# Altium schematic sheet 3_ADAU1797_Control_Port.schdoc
size 307 x 218 mm; Symbol: Drawing-Symbol_A4; Device: Drawing-Symbol_A4; @Project Name: Slowpoke; @Page Count: 7; @Update Date: 2025-12-13; @Create Date: 2025-12-13; @Schematic Name: Slowpoke_Sch; @Page No: 3; @Page Name: ADAU1797_Control_Port; Company: Analog Devices, Inc.; Version: V1.0; Page Size: A4; @Create Time: 14:28:30; @Update Time: 20:16:35; Width: 1170; Height: 825; Region Start: 1; X Region Count: 6; Y Region Count: 4; Blade Width: 10; Title Block Position: 3; @Board Name: Slowpoke
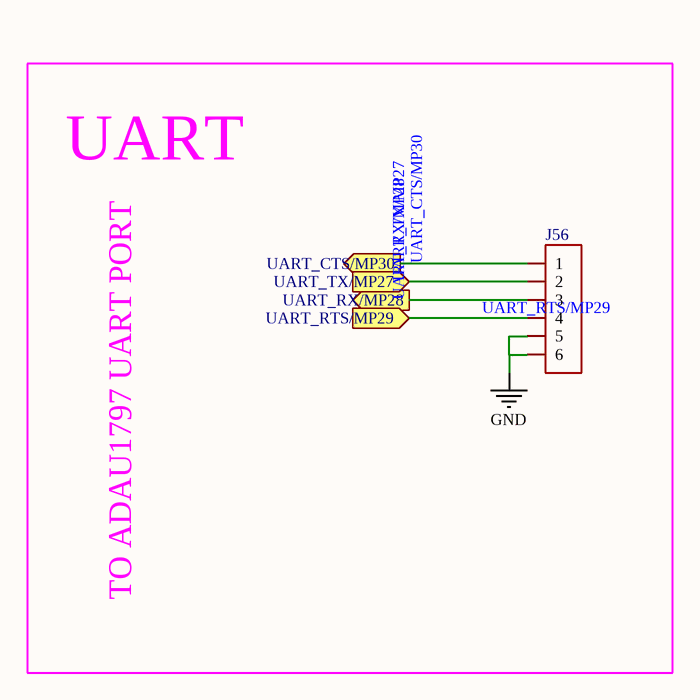
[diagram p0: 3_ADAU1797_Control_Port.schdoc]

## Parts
J56  2.54-1x6P直针  [HDR-TH_6P-P2.54-V-M-1]  (value not drawn)

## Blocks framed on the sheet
UART: J56

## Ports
UART_CTS/MP30 (out), UART_RTS/MP29 (in), UART_RX/MP28 (out), UART_TX/MP27 (in)

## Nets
GND: J56.5 J56.6
UART_CTS/MP30: J56.1 ; port UART_CTS/MP30
UART_RTS/MP29: J56.4 ; port UART_RTS/MP29
UART_RX/MP28: J56.3 ; port UART_RX/MP28
UART_TX/MP27: J56.2 ; port UART_TX/MP27

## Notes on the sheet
- TO ADAU1797 UART PORT

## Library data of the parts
J56 = 2.54-1x6P直针: Manufacturer: BOOMELE(博穆精密); Symbol: Header-Male-2.54_1x6; Add into BOM: yes; Pin Structure: 1x6P; Pitch: 2.54mm; Circluar Pins/Square Pins: Pin Header; Current Rating: 3A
